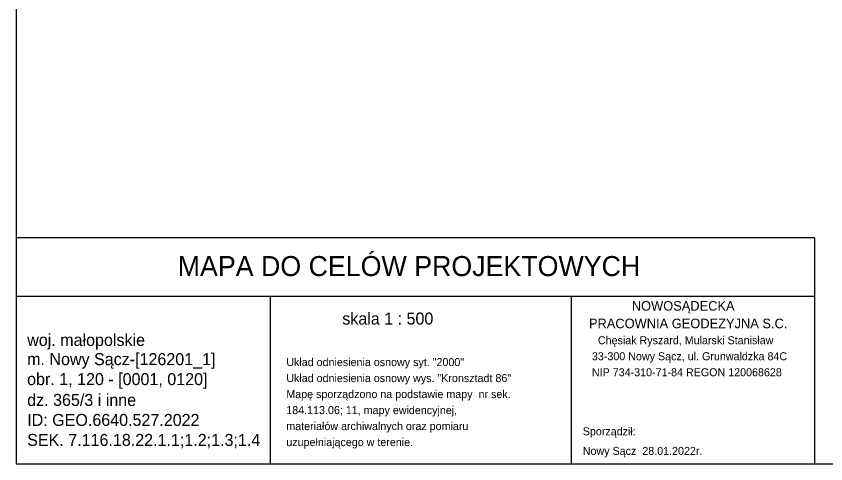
# Model space of a CAD drawing. Extents: x 7477803 to 7478145, y 5500698 to 5500984.
# Drawn here: x 7477803.3 to 7477904.4, y 5500697.6 to 5500753.5 of the extents above; entities that cross this region are included whole.
import ezdxf

# ---------------------------------------------------------------- set-up
doc = ezdxf.new("R2010")
doc.units = 0
doc.layers.add('robocza11', color=7, linetype='Continuous')
doc.layers.add('robocza50', color=7, linetype='Continuous')

msp = doc.modelspace()

# ---------------------------------------------------------------- linework, layer by layer
at = {"layer": 'robocza11'}
msp.add_lwpolyline([(7478015, 5500697.57), (7478144.73, 5500697.57), (7478144.73, 5500983.57), (7477803.26, 5500983.57), (7477803.26, 5500697.57), (7478010.82, 5500697.57)], close=True, dxfattribs=at)
at = {"layer": 'robocza50'}
for p, q in [((7477803.26, 5500718.53), (7477903.02, 5500718.53)), ((7477835.01, 5500697.57), (7477835.01, 5500718.53)), ((7477872.61, 5500697.57), (7477872.61, 5500718.53))]:
    msp.add_line(p, q, dxfattribs=at)
for points in [[(7477903.02, 5500725.83), (7477803.26, 5500725.83)], [(7477903.02, 5500697.57), (7477903.02, 5500725.82)], [(7477803.26, 5500697.57), (7477903.26, 5500697.57)]]:
    msp.add_lwpolyline(points, dxfattribs=at)

# ---------------------------------------------------------------- texts
for s, height, p in [('MAPA DO CELÓW PROJEKTOWYCH', 2.5, (7477823.43, 5500721.03)), ('            NOWOSĄDECKA', 1.2, (7477874.79, 5500716.71)), ('skala 1 : 500', 1.5, (7477843.98, 5500714.97)), ('PRACOWNIA GEODEZYJNA S.C.', 1.2, (7477874.79, 5500714.51)), ('woj. małopolskie', 1.5, (7477804.63, 5500712.3)), ('   Chęsiak Ryszard, Mularski Stanisław', 1, (7477874.79, 5500712.51)), ('Układ odniesienia osnowy syt. "2000"', 1, (7477836.99, 5500709.78)), (' 33-300 Nowy Sącz, ul. Grunwaldzka 84C', 1, (7477874.79, 5500710.51)), ('Układ odniesienia osnowy wys. "Kronsztadt 86"', 1, (7477836.99, 5500707.78)), (' NIP 734-310-71-84 REGON 120068628', 1, (7477874.79, 5500708.51)), ('Mapę sporządzono na podstawie mapy  nr sek.', 1, (7477836.99, 5500705.78)), ('184.113.06; 11, mapy ewidencyjnej, ', 1, (7477836.99, 5500703.78)), ('materiałów archiwalnych oraz pomiaru', 1, (7477836.99, 5500701.78)), ('Sporządził:', 1, (7477874.02, 5500701.13)), ('SEK. 7.116.18.22.1.1;1.2;1.3;1.4', 1.5, (7477804.63, 5500699.8)), ('uzupełniającego w terenie.', 1, (7477836.99, 5500699.78)), ('Nowy Sącz  28.01.2022r.', 1, (7477874.02, 5500698.68))]:
    msp.add_text(s, height=height, dxfattribs=at).set_placement(p)
for s, p in [('m. Nowy Sącz-[126201_1]', (7477804.62, 5500709.9)), ('obr. 1, 120 - [0001, 0120]', (7477804.62, 5500707.4)), ('dz. 365/3 i inne', (7477804.63, 5500704.8)), ('ID: GEO.6640.527.2022', (7477804.63, 5500702.3))]:
    msp.add_text(s, height=1.5, rotation=359.9961, dxfattribs=at).set_placement(p)

doc.saveas('drawing.dxf')
